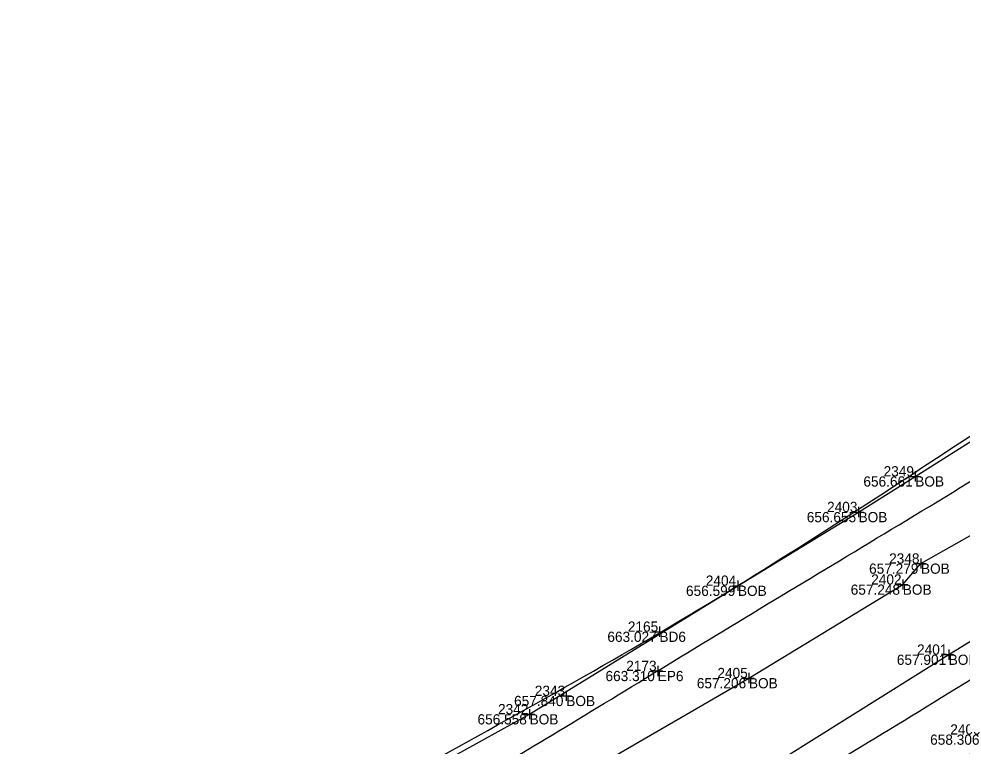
# Model space of a CAD drawing. Extents: x 2197382 to 2204062, y 634117 to 636522.
# Drawn here: x 2202538.2 to 2202630.7, y 635307.3 to 635378.5 of the extents above; entities that cross this region are included whole.
import ezdxf

# ---------------------------------------------------------------- set-up
doc = ezdxf.new("R2010")
doc.units = 0
for name, color, linetype in [('_CIVIL_CONSTRUCTION', 7, 'Continuous'), ('BR_X_SV_Bottom_of_Beam', 7, 'Continuous'), ('BR_X_SV_Bottom_of_Beam_Text', 7, 'Continuous'), ('BR_X_SV_Deck_Top', 7, 'Continuous'), ('BR_X_SV_Deck_Top_Text', 7, 'Continuous'), ('GE_P_Alignment_100_Distances', 7, 'Continuous'), ('SH_Border', 7, 'Continuous'), ('SH_Cut_Line', 7, 'Continuous'), ('SH_Data', 7, 'Continuous')]:
    doc.layers.add(name, color=color, linetype=linetype)

msp = doc.modelspace()

# ---------------------------------------------------------------- linework, layer by layer
at = {"layer": '_CIVIL_CONSTRUCTION'}
for p, q in [((2202625.572, 635333.707), (2202626.572, 635333.707)), ((2202626.072, 635334.207), (2202626.072, 635333.207)), ((2202626.072, 635333.707), (2202626.072, 635333.707)), ((2202620.015, 635330.213), (2202621.015, 635330.213)), ((2202620.515, 635330.713), (2202620.515, 635329.713)), ((2202620.515, 635330.213), (2202620.515, 635330.213)), ((2202626.632, 635325.663), (2202626.632, 635324.663)), ((2202626.132, 635325.163), (2202627.132, 635325.163)), ((2202626.632, 635325.163), (2202626.632, 635325.163)), ((2202608.693, 635323.492), (2202608.693, 635322.492)), ((2202624.848, 635323.608), (2202624.848, 635322.608)), ((2202608.193, 635322.992), (2202609.193, 635322.992)), ((2202608.693, 635322.992), (2202608.693, 635322.992)), ((2202624.348, 635323.108), (2202625.348, 635323.108)), ((2202624.848, 635323.108), (2202624.848, 635323.108)), ((2202601.002, 635318.987), (2202601.002, 635317.987)), ((2202600.502, 635318.487), (2202601.502, 635318.487)), ((2202601.002, 635318.487), (2202601.002, 635318.487)), ((2202628.849, 635316.236), (2202629.849, 635316.236)), ((2202629.349, 635316.736), (2202629.349, 635315.736)), ((2202629.349, 635316.236), (2202629.349, 635316.236)), ((2202600.336, 635314.64), (2202601.336, 635314.64)), ((2202600.836, 635315.14), (2202600.836, 635314.14)), ((2202600.836, 635314.64), (2202600.836, 635314.64)), ((2202609.773, 635314.44), (2202609.773, 635313.44)), ((2202609.273, 635313.94), (2202610.273, 635313.94)), ((2202609.773, 635313.94), (2202609.773, 635313.94)), ((2202591.879, 635312.698), (2202591.879, 635311.698)), ((2202591.379, 635312.198), (2202592.379, 635312.198)), ((2202591.879, 635312.198), (2202591.879, 635312.198)), ((2202588.283, 635310.899), (2202588.283, 635309.899)), ((2202587.783, 635310.399), (2202588.783, 635310.399)), ((2202588.283, 635310.399), (2202588.283, 635310.399))]:
    msp.add_line(p, q, dxfattribs=at)
at = {"layer": 'BR_X_SV_Bottom_of_Beam'}
for points in [[(2202513.324, 635270.745), (2202518.461, 635273.222), (2202532.26, 635280.283), (2202548.237, 635288.645), (2202560.651, 635295.117), (2202588.283, 635310.399), (2202608.693, 635322.992), (2202620.515, 635330.213), (2202626.072, 635333.707), (2202636.254, 635340.133), (2202656.933, 635353.888), (2202662.455, 635358.969), (2202720.902, 635399.769), (2202735.154, 635410.438), (2202760.7, 635432.077)], [(2202624.848, 635323.108), (2202626.632, 635325.163), (2202640.898, 635333.252), (2202660.713, 635346.321), (2202681.445, 635361.418), (2202700.993, 635375.17), (2202725.622, 635393.015), (2202741.163, 635404.571), (2202768.027, 635427.422)], [(2202600.025, 635298.569), (2202613.195, 635306.135), (2202629.349, 635316.236), (2202645.46, 635326.182), (2202658.228, 635335.017), (2202675.533, 635345.812), (2202692.151, 635358.452)], [(2202572.867, 635292.536), (2202609.773, 635313.94), (2202624.848, 635323.108)]]:
    msp.add_lwpolyline(points, dxfattribs=at)
at = {"layer": 'BR_X_SV_Deck_Top'}
for points in [[(2202430.051, 635233.588), (2202439.74, 635238.507), (2202466.339, 635247.691), (2202507.168, 635268.028), (2202543.723, 635286.397), (2202574.877, 635303.715), (2202604.911, 635320.157), (2202634.127, 635339.4), (2202663.018, 635358.594), (2202692.445, 635376.507), (2202729.246, 635404.451), (2202755.806, 635426.417), (2202769.739, 635438.84)], [(2202458.051, 635216.681), (2202477.116, 635219.979), (2202511.723, 635243.78), (2202554.955, 635262.299), (2202588.014, 635280.674), (2202608.342, 635292.387), (2202640.833, 635312.137), (2202668.147, 635329.948), (2202698.573, 635351.315), (2202722.135, 635368.649), (2202754.604, 635393.426), (2202777.494, 635412.293), (2202789.607, 635422.635)], [(2202895.365, 635391.811), (2202885.347, 635387.334), (2202865.192, 635377.205), (2202839.037, 635363.762), (2202813.103, 635349.723), (2202789.18, 635336.138), (2202762.388, 635320.287), (2202740.668, 635306.565), (2202716.628, 635290.831), (2202693.394, 635275.343), (2202664.567, 635254.787), (2202633.536, 635231.765), (2202595.89, 635201.643), (2202569.397, 635178.622), (2202555.165, 635165.675)], [(2202923.181, 635376.197), (2202906.167, 635369.085), (2202881.487, 635355.934), (2202846.739, 635338.13), (2202819.013, 635322.649), (2202790.142, 635306.09), (2202754.022, 635283.778), (2202709.422, 635255.583), (2202663.285, 635220.884), (2202620.566, 635187.914), (2202595.285, 635167.396), (2202582.509, 635156.81)]]:
    msp.add_open_spline(points, degree=3, dxfattribs=at)
at = {"layer": 'GE_P_Alignment_100_Distances'}
for points in [[(2202483.163, 635252.761), (2202495.402, 635258.227), (2202515.209, 635267.824), (2202539.505, 635280.183), (2202556.272, 635289.074), (2202570.794, 635297.089), (2202585.76, 635305.335), (2202607.83, 635319.01), (2202630.778, 635332.646), (2202656.431, 635348.815), (2202675.69, 635362.468), (2202698.981, 635379.185), (2202729.904, 635401.353), (2202753.674, 635420.874), (2202767.823, 635433.185)], [(2202457.668, 635223.282), (2202466.48, 635226.872), (2202500.455, 635242.355), (2202539.476, 635261.183), (2202573.06, 635279.52), (2202585.609, 635286.631), (2202599.84, 635294.842), (2202617.618, 635305.231), (2202642.294, 635320.395), (2202667.372, 635336.77), (2202691.723, 635353.633), (2202713.413, 635369.403), (2202739.641, 635388.973), (2202758.657, 635404.276), (2202770.061, 635413.813)], [(2202926.993, 635398.223), (2202911.054, 635391.267), (2202884.78, 635379.221), (2202850.251, 635362.173), (2202828.215, 635350.038), (2202808.09, 635339.198), (2202790.855, 635329.045), (2202764, 635313.325), (2202738.781, 635297.635), (2202713.051, 635280.577), (2202697.019, 635269.602), (2202684.529, 635260.864), (2202668.986, 635249.754), (2202642.65, 635230.806), (2202596.561, 635193.887), (2202560.681, 635163.156), (2202538.312, 635142.813)], [(2202919.499, 635378.368), (2202901.447, 635370.678), (2202875.936, 635356.879), (2202844.592, 635341.598), (2202825.856, 635330.823), (2202809.466, 635322.019), (2202780.051, 635304.409), (2202746.062, 635282.999), (2202707.717, 635258.176), (2202682.244, 635240.209), (2202658.947, 635222.257), (2202614.143, 635189.251), (2202577.354, 635157.516), (2202549.508, 635131.427)]]:
    msp.add_open_spline(points, degree=3, dxfattribs=at)

# ---------------------------------------------------------------- texts
at = {"layer": 'BR_X_SV_Bottom_of_Beam_Text'}
for s, p in [('2349', (2202622.97, 635333.707)), ('656.661', (2202620.99, 635332.707)), ('BOB', (2202626.072, 635332.707)), ('2403', (2202617.432, 635330.213)), ('656.655', (2202615.445, 635329.213)), ('BOB', (2202620.515, 635329.213)), ('2348', (2202623.513, 635325.163)), ('657.279', (2202621.548, 635324.163)), ('BOB', (2202626.632, 635324.163)), ('2404', (2202605.552, 635322.992)), ('2402', (2202621.756, 635323.108)), ('656.599', (2202603.609, 635321.992)), ('BOB', (2202608.693, 635321.992)), ('657.248', (2202619.748, 635322.108)), ('BOB', (2202624.848, 635322.108)), ('2401', (2202626.249, 635316.236)), ('657.901', (2202624.267, 635315.236)), ('BOB', (2202629.349, 635315.236)), ('2405', (2202606.684, 635313.94)), ('657.206', (2202604.669, 635312.94)), ('BOB', (2202609.773, 635312.94)), ('2343', (2202588.796, 635312.198)), ('657.840', (2202586.765, 635311.198)), ('BOB', (2202591.879, 635311.198)), ('2342', (2202585.191, 635310.399)), ('656.558', (2202583.183, 635309.399)), ('BOB', (2202588.283, 635309.399)), ('2400', (2202629.504, 635308.407)), ('658.306', (2202627.532, 635307.407))]:
    msp.add_text(s, height=1, dxfattribs=at).set_placement(p)
at = {"layer": 'BR_X_SV_Deck_Top_Text'}
for s, p in [('2165', (2202597.913, 635318.487)), ('663.027', (2202595.906, 635317.487)), ('BD6', (2202601.002, 635317.487))]:
    msp.add_text(s, height=1, dxfattribs=at).set_placement(p)
at = {"layer": 'SH_Border'}
msp.add_text('EP6', height=1, dxfattribs=at).set_placement((2202600.836, 635313.64))
at = {"layer": 'SH_Cut_Line'}
msp.add_text('2173', height=1, dxfattribs=at).set_placement((2202597.753, 635314.64))
at = {"layer": 'SH_Data'}
msp.add_text('663.310', height=1, dxfattribs=at).set_placement((2202595.722, 635313.64))

doc.saveas('drawing.dxf')
